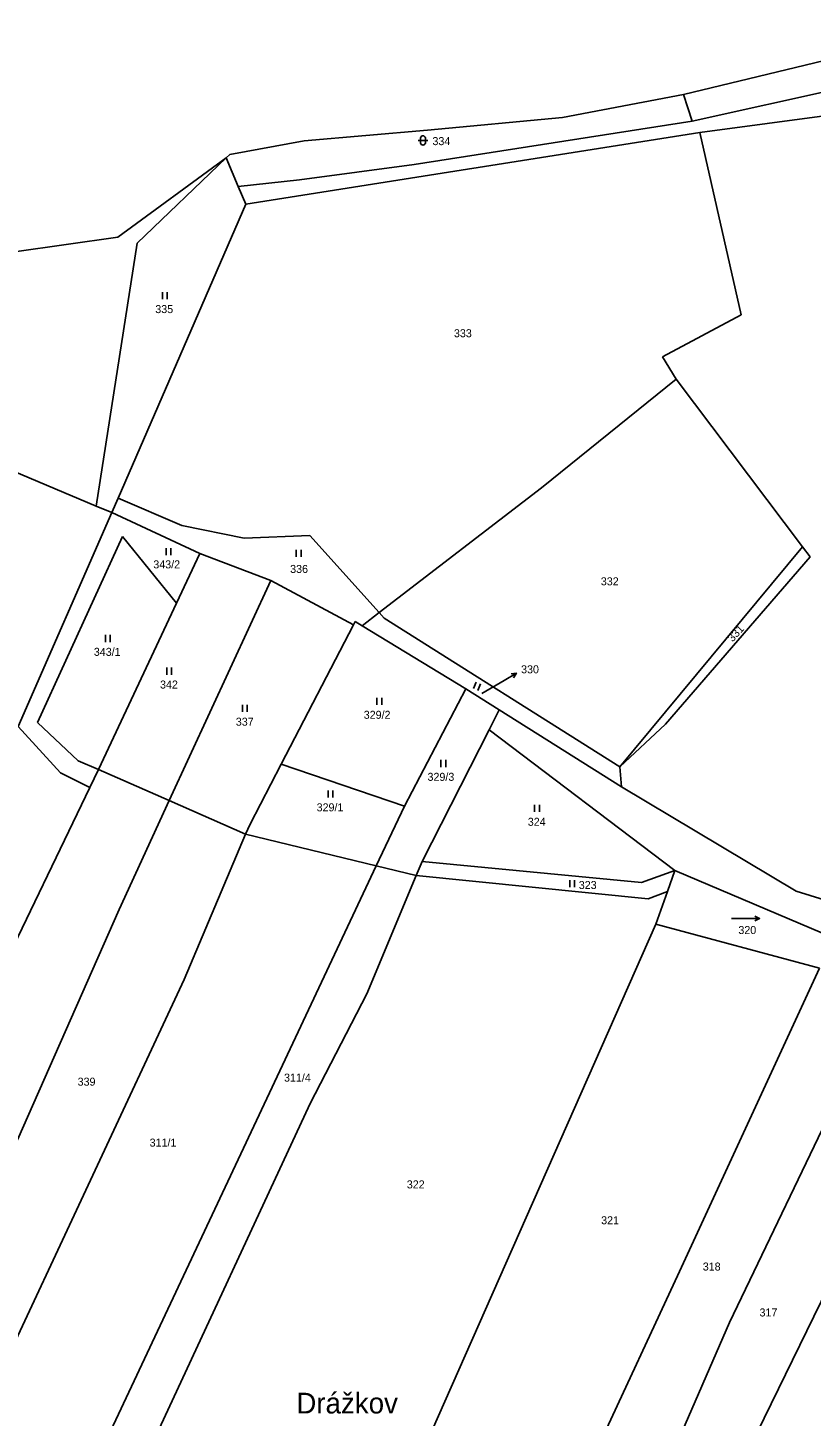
# Model space of a CAD drawing. Extents: x -760642 to -757221, y -1092371 to -1088855.
# Drawn here: x -759171 to -759004.6, y -1089681.5 to -1089386.6 of the extents above; entities that cross this region are included whole.
import ezdxf

# ---------------------------------------------------------------- set-up
doc = ezdxf.new("R2010")
doc.units = 0
for name, color, linetype in [('Vrstva 1', 7, 'Continuous'), ('Vrstva 15', 7, 'Continuous'), ('Vrstva 16', 7, 'Continuous'), ('Vrstva 18', 7, 'Continuous'), ('Vrstva 25', 7, 'Continuous')]:
    doc.layers.add(name, color=color, linetype=linetype)

msp = doc.modelspace()

# ---------------------------------------------------------------- linework, layer by layer
at = {"layer": 'Vrstva 1'}
for p, q in [((-759029.85, -1089406.38), (-758940.61, -1089386.57)), ((-759031.69, -1089400.74), (-758993.67, -1089391.57)), ((-759057.42, -1089405.64), (-759031.69, -1089400.74)), ((-759029.85, -1089406.38), (-759031.69, -1089400.74)), ((-759088.93, -1089415.58), (-759029.85, -1089406.38)), ((-759086.05, -1089408.34), (-759057.42, -1089405.64)), ((-759028.28, -1089408.84), (-758999.66, -1089404.98)), ((-759128.09, -1089413.52), (-759112.3, -1089410.57)), ((-759124.66, -1089424.06), (-759028.28, -1089408.84)), ((-759112.3, -1089410.57), (-759086.05, -1089408.34)), ((-759028.28, -1089408.84), (-759019.51, -1089447.52)), ((-759128.84, -1089414.23), (-759128.09, -1089413.52)), ((-759151.87, -1089431.08), (-759128.84, -1089414.23)), ((-759147.72, -1089432.32), (-759128.84, -1089414.23)), ((-759128.84, -1089414.23), (-759126.26, -1089420.29)), ((-759113.27, -1089418.86), (-759088.93, -1089415.58)), ((-759126.26, -1089420.29), (-759113.27, -1089418.86)), ((-759126.26, -1089420.29), (-759124.66, -1089424.06)), ((-759124.66, -1089424.06), (-759151.78, -1089486.53)), ((-759173.76, -1089434.2), (-759151.87, -1089431.08)), ((-759147.72, -1089432.32), (-759156.44, -1089488.16)), ((-759019.51, -1089447.52), (-759036.21, -1089456.49)), ((-759036.21, -1089456.49), (-759033.28, -1089461.23)), ((-759033.28, -1089461.23), (-759061.86, -1089484.31)), ((-759033.28, -1089461.23), (-759006.42, -1089496.85)), ((-759179.12, -1089478.63), (-759156.44, -1089488.16)), ((-759061.86, -1089484.31), (-759096.38, -1089510.77)), ((-759151.78, -1089486.53), (-759153.09, -1089489.57)), ((-759151.78, -1089486.53), (-759138.23, -1089492.27)), ((-759153.09, -1089489.57), (-759173.03, -1089534.97)), ((-759156.44, -1089488.16), (-759153.09, -1089489.57)), ((-759153.09, -1089489.57), (-759134.42, -1089498.28)), ((-759138.23, -1089492.27), (-759124.99, -1089495.02)), ((-759150.88, -1089494.61), (-759168.9, -1089534.18)), ((-759150.88, -1089494.61), (-759139.37, -1089508.82)), ((-759124.99, -1089495.02), (-759111.1, -1089494.45)), ((-759096.38, -1089510.77), (-759111.1, -1089494.45)), ((-759134.42, -1089498.28), (-759139.37, -1089508.82)), ((-759134.42, -1089498.28), (-759119.35, -1089503.97)), ((-759045.26, -1089543.55), (-759006.42, -1089496.85)), ((-759004.83, -1089498.99), (-759035.57, -1089534.53)), ((-759006.42, -1089496.85), (-759004.83, -1089498.99)), ((-759119.35, -1089503.97), (-759140.92, -1089550.75)), ((-759119.35, -1089503.97), (-759101.81, -1089513.37)), ((-759139.37, -1089508.82), (-759155.94, -1089544.16)), ((-759096.38, -1089510.77), (-759099.97, -1089513.59)), ((-759095.26, -1089512.02), (-759096.38, -1089510.77)), ((-759101.81, -1089513.37), (-759117.18, -1089543.03)), ((-759101.46, -1089512.68), (-759101.81, -1089513.37)), ((-759101.46, -1089512.68), (-759099.97, -1089513.59)), ((-759099.97, -1089513.59), (-759077.96, -1089527.01)), ((-759095.26, -1089512.02), (-759045.26, -1089543.55)), ((-759077.96, -1089527.01), (-759090.98, -1089551.91)), ((-759077.96, -1089527.01), (-759070.84, -1089531.45)), ((-759070.84, -1089531.45), (-759072.97, -1089535.72)), ((-759070.84, -1089531.45), (-759044.86, -1089547.81)), ((-759168.9, -1089534.18), (-759160.28, -1089542.29)), ((-759173.03, -1089534.97), (-759164, -1089544.87)), ((-759072.97, -1089535.72), (-759087.21, -1089563.66)), ((-759072.97, -1089535.72), (-759033.53, -1089565.61)), ((-759035.57, -1089534.53), (-759045.26, -1089543.55)), ((-759160.28, -1089542.29), (-759155.94, -1089544.16)), ((-759117.18, -1089543.03), (-759123.77, -1089555.77)), ((-759090.98, -1089551.91), (-759117.18, -1089543.03)), ((-759164, -1089544.87), (-759157.78, -1089547.94)), ((-759155.94, -1089544.16), (-759157.78, -1089547.94)), ((-759155.94, -1089544.16), (-759140.92, -1089550.75)), ((-759045.26, -1089543.55), (-759044.86, -1089547.81)), ((-759157.78, -1089547.94), (-759191.32, -1089617.58)), ((-759044.86, -1089547.81), (-759007.8, -1089570)), ((-759140.92, -1089550.75), (-759151.59, -1089573.9)), ((-759140.92, -1089550.75), (-759124.73, -1089557.84)), ((-759090.98, -1089551.91), (-759096.95, -1089564.61)), ((-759124.73, -1089557.84), (-759137.76, -1089588.73)), ((-759123.77, -1089555.77), (-759124.73, -1089557.84)), ((-759124.73, -1089557.84), (-759096.95, -1089564.61)), ((-759087.21, -1089563.66), (-759088.47, -1089566.68)), ((-759087.21, -1089563.66), (-759040.62, -1089568.12)), ((-759096.95, -1089564.61), (-759157.11, -1089692.62)), ((-759088.47, -1089566.68), (-759098.94, -1089591.8)), ((-759096.95, -1089564.61), (-759088.47, -1089566.68)), ((-759088.47, -1089566.68), (-759039.19, -1089571.61)), ((-759040.62, -1089568.12), (-759033.53, -1089565.61)), ((-759035.12, -1089570.05), (-759033.53, -1089565.61)), ((-759033.53, -1089565.61), (-758999.85, -1089579.87)), ((-759039.19, -1089571.61), (-759035.12, -1089570.05)), ((-759037.62, -1089577.02), (-759035.12, -1089570.05)), ((-759007.8, -1089570), (-758973.16, -1089580.73)), ((-759151.59, -1089573.9), (-759173.17, -1089622.82)), ((-759096.62, -1089710.57), (-759037.62, -1089577.02)), ((-759002.84, -1089586.33), (-759037.62, -1089577.02)), ((-759002.84, -1089586.33), (-759032.57, -1089650.79)), ((-759137.76, -1089588.73), (-759183.07, -1089685.78)), ((-759098.94, -1089591.8), (-759111.02, -1089615.06)), ((-758987.98, -1089590.7), (-759021.95, -1089661.61)), ((-758972.3, -1089595.3), (-759036.93, -1089727.6)), ((-759111.02, -1089615.06), (-759148.06, -1089695)), ((-759032.57, -1089650.79), (-759064.96, -1089720.38)), ((-759021.95, -1089661.61), (-759049.74, -1089725.28))]:
    msp.add_line(p, q, dxfattribs=at)
at = {"layer": 'Vrstva 16'}
for p, q in [((-759074.52, -1089528.02), (-759069.79, -1089525.23)), ((-759069.79, -1089525.23), (-759067.207, -1089523.704))]:
    msp.add_line(p, q, dxfattribs=at)
msp.add_lwpolyline([(-759068.323, -1089523.782), (-759067.207, -1089523.704), (-759067.814, -1089524.643)], dxfattribs=at)
at = {"layer": 'Vrstva 25'}
for p, q in [((-759088.04, -1089410.5), (-759086.04, -1089410.5)), ((-759087.54, -1089411), (-759087.54, -1089410)), ((-759086.54, -1089411), (-759086.54, -1089410)), ((-759142.387, -1089442.745), (-759142.387, -1089444.245)), ((-759141.365, -1089444.245), (-759141.365, -1089442.745)), ((-759141.597, -1089497.095), (-759141.597, -1089498.595)), ((-759140.575, -1089498.595), (-759140.575, -1089497.095)), ((-759113.957, -1089497.445), (-759113.957, -1089498.945)), ((-759112.935, -1089498.945), (-759112.935, -1089497.445)), ((-759154.487, -1089515.555), (-759154.487, -1089517.055)), ((-759153.465, -1089517.055), (-759153.465, -1089515.555)), ((-759141.437, -1089522.495), (-759141.437, -1089523.995)), ((-759140.415, -1089523.995), (-759140.415, -1089522.495)), ((-759075.752, -1089525.56), (-759076.335, -1089526.942)), ((-759075.393, -1089527.34), (-759074.81, -1089525.958)), ((-759125.367, -1089530.395), (-759125.367, -1089531.895)), ((-759124.345, -1089531.895), (-759124.345, -1089530.395)), ((-759096.817, -1089528.925), (-759096.817, -1089530.425)), ((-759095.795, -1089530.425), (-759095.795, -1089528.925)), ((-759083.247, -1089542.105), (-759083.247, -1089543.605)), ((-759082.225, -1089543.605), (-759082.225, -1089542.105)), ((-759107.187, -1089548.585), (-759107.187, -1089550.085)), ((-759106.165, -1089550.085), (-759106.165, -1089548.585)), ((-759063.347, -1089551.655), (-759063.347, -1089553.155)), ((-759062.325, -1089553.155), (-759062.325, -1089551.655)), ((-759055.887, -1089567.655), (-759055.887, -1089569.155)), ((-759054.865, -1089569.155), (-759054.865, -1089567.655)), ((-759021.56, -1089575.79), (-759015.56, -1089575.79))]:
    msp.add_line(p, q, dxfattribs=at)
msp.add_lwpolyline([(-759016.56, -1089575.29), (-759015.56, -1089575.79), (-759016.56, -1089576.29)], dxfattribs=at)
for centre, start, end in [((-759087.04, -1089410), 0, 180), ((-759087.04, -1089411), 180, 0)]:
    msp.add_arc(centre, 0.5, start, end, dxfattribs=at)

# ---------------------------------------------------------------- texts
at = {"layer": 'Vrstva 15'}
msp.add_text('Drážkov', height=4.4, dxfattribs=at).set_placement((-759113.94, -1089680.93))
at = {"layer": 'Vrstva 16'}
msp.add_text('330', height=1.7, dxfattribs=at).set_placement((-759066.21, -1089523.7))
at = {"layer": 'Vrstva 18'}
for s, p in [('334', (-759085.038, -1089411.5)), ('335', (-759143.89, -1089447.18)), ('333', (-759080.47, -1089452.31)), ('343/2', (-759144.31, -1089501.41)), ('336', (-759115.25, -1089502.38)), ('332', (-759049.28, -1089505.01)), ('343/1', (-759156.94, -1089519.99)), ('342', (-759142.88, -1089526.93)), ('337', (-759126.79, -1089534.83)), ('329/2', (-759099.63, -1089533.36)), ('329/3', (-759086.08, -1089546.54)), ('329/1', (-759109.63, -1089553.02)), ('324', (-759064.79, -1089556.09)), ('323', (-759053.96, -1089569.52)), ('320', (-759020.07, -1089579.09)), ('339', (-759160.38, -1089611.3)), ('311/4', (-759116.55, -1089610.44)), ('311/1', (-759145.09, -1089624.24)), ('322', (-759090.48, -1089633.12)), ('321', (-759049.21, -1089640.74)), ('318', (-759027.63, -1089650.57)), ('317', (-759015.58, -1089660.32))]:
    msp.add_text(s, height=1.7, dxfattribs=at).set_placement(p)
for s, height, rotation, p in [('331', 1.7, 47.59605, (-759021.29, -1089517.15)), ('330', 0.1, 337.12191, (-759074.52, -1089528.02))]:
    msp.add_text(s, height=height, rotation=rotation, dxfattribs=at).set_placement(p)

doc.saveas('drawing.dxf')
